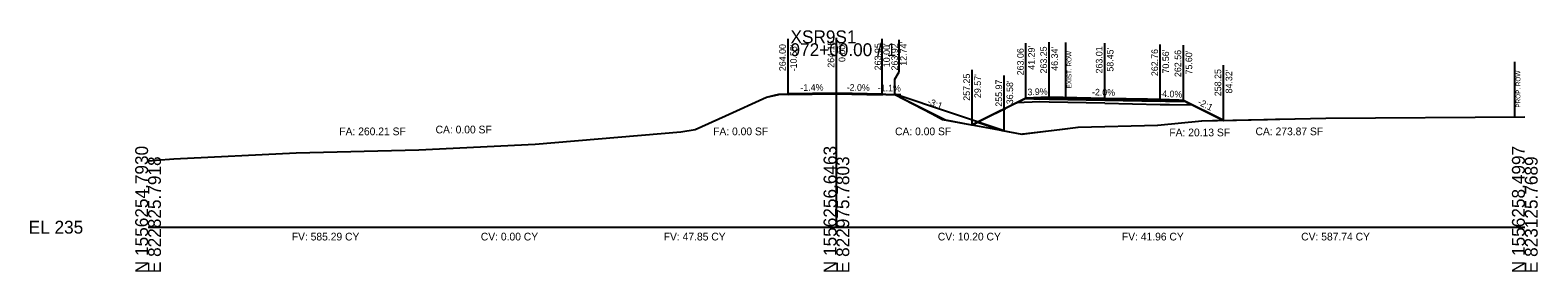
# Model space of a CAD drawing. Extents: x -26 to 823017, y -16 to 1558356.
# Drawn here: x 1974.3 to 2302.8, y 2990.3 to 3042.8 of the extents above; entities that cross this region are included whole.
import ezdxf

# ---------------------------------------------------------------- set-up
doc = ezdxf.new("R2010")
doc.units = 0
for name, color, linetype in [('ASPHALT_19MM1', 7, 'Continuous'), ('CONST_DCH', 7, 'Continuous'), ('CONST_LV3', 7, 'Continuous'), ('Draft_XS_Grid', 7, 'Continuous'), ('DTM_CORRIDOR', 7, 'Continuous'), ('DTM_P_FINISHED_GRADE2', 7, 'Continuous'), ('DTM_X_GROUND', 7, 'Continuous'), ('SLOPE_STAKES_FILL', 7, 'Continuous'), ('X_PROFILES_1', 7, 'Continuous'), ('X_TRANS_EOP', 7, 'Continuous'), ('XS_CELL', 7, 'Continuous'), ('XS_P_ASPHALT', 7, 'Continuous'), ('XS_P_DR_GRAVEL', 7, 'Continuous'), ('XS_P_GROUND', 7, 'Continuous'), ('XS_P_NULL_POINT', 7, 'Continuous'), ('XS_P_ROW', 7, 'Continuous'), ('XS_P_SHOULDER', 7, 'Continuous'), ('XS_P_SUBGRADE_GRANULAR', 7, 'Continuous'), ('XS_P_SUBGRADE_LEVELING', 7, 'Continuous'), ('XS_P_SUBGRADE_MILLING', 7, 'Continuous'), ('XS_P_SUBGRADE_UNDERCUT', 7, 'Continuous'), ('XS_P_TX_CLEARZONE', 7, 'Continuous'), ('XS_P_TX_FS_BS', 7, 'Continuous'), ('XS_SHEET_EW_TX_AREA', 7, 'Continuous'), ('XS_SHEET_EW_TX_VOLUME', 7, 'Continuous'), ('XS_X_ROW', 7, 'Continuous')]:
    doc.layers.add(name, color=color, linetype=linetype)

msp = doc.modelspace()

# ---------------------------------------------------------------- linework, layer by layer
at = {"layer": 'ASPHALT_19MM1'}
msp.add_lwpolyline([(2196.34, 3027.88), (2208.45, 3027.63), (2220.56, 3027.39), (2220.56, 3027.6), (2208.45, 3027.84), (2196.34, 3028.09), (2196.34, 3027.88)], dxfattribs=at)
at = {"layer": 'CONST_LV3'}
for points in [[(2150, 3029.15), (2164, 3028.87)], [(2000, 3014.41), (2001.8, 3014.55), (2005.65, 3014.87), (2032.3, 3016.21), (2058.98, 3016.83), (2084.32, 3018.03), (2116.06, 3020.73), (2119.18, 3021.23), (2125.84, 3024.24), (2134.73, 3028.25), (2136.51, 3028.72), (2137.45, 3028.96), (2137.45, 3028.96), (2137.45, 3028.96), (2137.45, 3028.96)], [(2162.74, 3028.92), (2162.74, 3028.92), (2164, 3028.87)], [(2173.76, 3023.34), (2173.76, 3023.34), (2173.78, 3023.34), (2179.44, 3022.28), (2179.47, 3022.27), (2179.57, 3022.25), (2179.79, 3022.36), (2183.24, 3024.07), (2185.93, 3025.4), (2186.82, 3025.84), (2186.86, 3025.86), (2191.29, 3028.06), (2194.56, 3028.18), (2196.34, 3028.25), (2204.83, 3028.08), (2208.45, 3028.01), (2211.6, 3027.85), (2220.56, 3027.39), (2224.62, 3027.53), (2225.6, 3027.56), (2226.86, 3026.94), (2227.01, 3026.86), (2228.29, 3026.23), (2229.88, 3025.44), (2234.35, 3023.23), (2236.77, 3023.3), (2237.15, 3023.31), (2243.57, 3023.44), (2243.9, 3023.44), (2245.64, 3023.48), (2245.87, 3023.48), (2246.39, 3023.49), (2246.54, 3023.5), (2246.59, 3023.5), (2256.64, 3023.7), (2300, 3024.02)], [(2179.57, 3022.25), (2186.86, 3025.86), (2191.29, 3028.06), (2194.56, 3028.18), (2196.34, 3028.25)], [(2225.63, 3027.56), (2234.32, 3023.25)]]:
    msp.add_lwpolyline(points, dxfattribs=at)
at = {"layer": 'DTM_P_FINISHED_GRADE2'}
msp.add_lwpolyline([(2137.45, 3028.85), (2137.45, 3028.85), (2137.45, 3028.85), (2139.45, 3028.94), (2139.45, 3028.93), (2150, 3029.15), (2150, 3029.15), (2160, 3028.95), (2160, 3028.95), (2160, 3028.95), (2160.74, 3028.93), (2162.74, 3028.85), (2162.74, 3028.85), (2162.74, 3028.85), (2173.76, 3023.34)], dxfattribs=at)
at = {"layer": 'DTM_X_GROUND'}
for points in [[(2000, 3014.41), (2001.8, 3014.55), (2005.65, 3014.87), (2032.3, 3016.21), (2058.98, 3016.83), (2084.32, 3018.03), (2116.06, 3020.73), (2119.18, 3021.23), (2125.84, 3024.24), (2134.73, 3028.25), (2136.51, 3028.72), (2137.47, 3028.97), (2147.38, 3029.11), (2150.14, 3029.15), (2160.79, 3028.89), (2162.73, 3028.85), (2170.86, 3024.63), (2173.1, 3023.46), (2184.29, 3021.39), (2190.38, 3020.26), (2190.65, 3020.3), (2198.7, 3021.27), (2202.66, 3021.75), (2220.06, 3022.22), (2229.64, 3023.16), (2246.54, 3023.5), (2256.64, 3023.7), (2300, 3024.02)], [(2000, 3014.41), (2001.8, 3014.55), (2005.65, 3014.87), (2032.3, 3016.21), (2058.98, 3016.83), (2084.32, 3018.03), (2116.06, 3020.73), (2119.18, 3021.23), (2125.84, 3024.24), (2134.73, 3028.25), (2136.51, 3028.72), (2137.47, 3028.97), (2147.38, 3029.11), (2150.14, 3029.15), (2160.79, 3028.89), (2162.73, 3028.85), (2170.86, 3024.63), (2173.1, 3023.46), (2179.44, 3022.28), (2179.57, 3022.25), (2179.79, 3022.36), (2183.24, 3024.07), (2185.93, 3025.4), (2186.82, 3025.84), (2186.86, 3025.86), (2191.29, 3028.06), (2194.56, 3028.18), (2196.34, 3028.25), (2204.83, 3028.08), (2208.45, 3028.01), (2211.6, 3027.85), (2220.56, 3027.39), (2224.62, 3027.53), (2225.6, 3027.56), (2226.86, 3026.94), (2227.01, 3026.86), (2228.29, 3026.23), (2229.88, 3025.44), (2234.35, 3023.23), (2236.77, 3023.3), (2237.15, 3023.31), (2243.57, 3023.44), (2243.9, 3023.44), (2245.64, 3023.48), (2245.87, 3023.48), (2246.39, 3023.49), (2246.54, 3023.5), (2246.59, 3023.5), (2256.64, 3023.7), (2300, 3024.02)], [(2000, 3014.41), (2001.8, 3014.55), (2005.65, 3014.87), (2032.3, 3016.21), (2058.98, 3016.83), (2084.32, 3018.03), (2116.06, 3020.73), (2119.18, 3021.23), (2125.84, 3024.24), (2134.73, 3028.25), (2136.51, 3028.65), (2137.45, 3028.85), (2137.45, 3028.85), (2137.45, 3028.85), (2137.45, 3028.85), (2137.45, 3028.85), (2137.45, 3028.85), (2139.45, 3028.94), (2139.45, 3028.93), (2150, 3029.15), (2150, 3029.15), (2160, 3028.95), (2160, 3028.95), (2160, 3028.95), (2160, 3028.95), (2160, 3028.95), (2160, 3028.95), (2160.74, 3028.93), (2162.74, 3028.85), (2162.74, 3028.85), (2162.74, 3028.85), (2173.76, 3023.34), (2173.76, 3023.34), (2173.76, 3023.34), (2173.78, 3023.34), (2179.44, 3022.28), (2179.47, 3022.27), (2179.57, 3022.25), (2179.79, 3022.36), (2183.24, 3024.07), (2185.93, 3025.4), (2186.82, 3025.84), (2186.86, 3025.86), (2191.29, 3028.06), (2194.56, 3028.18), (2196.34, 3028.25), (2204.83, 3028.08), (2208.45, 3028.01), (2211.6, 3027.85), (2220.56, 3027.39), (2224.62, 3027.53), (2225.6, 3027.56), (2226.86, 3026.94), (2227.01, 3026.86), (2228.29, 3026.23), (2229.88, 3025.44), (2234.35, 3023.23), (2236.77, 3023.3), (2237.15, 3023.31), (2243.57, 3023.44), (2243.9, 3023.44), (2245.64, 3023.48), (2245.87, 3023.48), (2246.39, 3023.49), (2246.54, 3023.5), (2246.59, 3023.5), (2256.64, 3023.7), (2300, 3024.02)]]:
    msp.add_lwpolyline(points, dxfattribs=at)
at = {"layer": 'X_TRANS_EOP'}
msp.add_lwpolyline([(2196.34, 3028.09), (2208.45, 3027.84), (2220.56, 3027.6), (2220.56, 3027.76), (2208.45, 3028.01), (2196.34, 3028.25), (2196.34, 3028.09)], dxfattribs=at)
at = {"layer": 'XS_CELL'}
for p, q in [((2150, 3000), (2150, 3040)), ((2000, 3000), (2150, 3000)), ((2150, 3000), (2300, 3000))]:
    msp.add_line(p, q, dxfattribs=at)
at = {"layer": 'XS_P_ASPHALT'}
msp.add_lwpolyline([(2139.45, 3028.87), (2139.45, 3028.87), (2150, 3029.02), (2150, 3029.02), (2160, 3028.82), (2160, 3028.82), (2160, 3028.82), (2160, 3028.95), (2160, 3028.95), (2150, 3029.15), (2150, 3029.15), (2139.45, 3029), (2139.45, 3028.87)], dxfattribs=at)
at = {"layer": 'XS_P_DR_GRAVEL'}
for points in [[(2194.56, 3028.18), (2191.29, 3028.06), (2191.24, 3028.03), (2191.15, 3027.98), (2193.01, 3027.95), (2196.34, 3027.88), (2196.34, 3028.13), (2196.34, 3028.25), (2194.56, 3028.18)], [(2221.61, 3027.72), (2225.6, 3027.56), (2225.71, 3027.51), (2226.18, 3027.28), (2221.73, 3027.37), (2220.56, 3027.39), (2220.56, 3027.68), (2220.56, 3027.76), (2221.61, 3027.72)]]:
    msp.add_lwpolyline(points, dxfattribs=at)
at = {"layer": 'XS_P_GROUND'}
for points in [[(2186.58, 3020.97), (2162.74, 3028.92), (2162.74, 3028.92)], [(2191.29, 3028.06), (2179.57, 3022.25)], [(2225.6, 3027.56), (2234.35, 3023.23)], [(2186.58, 3020.97), (2186.58, 3020.97), (2190.38, 3020.26), (2190.65, 3020.3), (2190.65, 3020.3), (2198.7, 3021.27), (2198.7, 3021.27), (2202.66, 3021.75), (2202.66, 3021.75), (2220.06, 3022.22), (2220.06, 3022.22), (2229.64, 3023.16), (2229.64, 3023.16), (2234.32, 3023.25), (2234.32, 3023.25)], [(2186.58, 3020.97), (2186.58, 3020.97), (2190.38, 3020.26), (2190.65, 3020.3), (2190.65, 3020.3), (2198.7, 3021.27), (2198.7, 3021.27), (2202.66, 3021.75), (2202.66, 3021.75), (2220.06, 3022.22), (2220.06, 3022.22), (2229.64, 3023.16), (2229.64, 3023.16), (2234.32, 3023.25), (2234.32, 3023.25)]]:
    msp.add_lwpolyline(points, dxfattribs=at)
at = {"layer": 'XS_P_ROW'}
msp.add_line((2297.83, 3024), (2297.83, 3036), dxfattribs=at)
at = {"layer": 'XS_P_SHOULDER'}
for points in [[(2191.29, 3028.06), (2194.56, 3028.18), (2196.34, 3028.25)], [(2225.6, 3027.56), (2221.61, 3027.72), (2220.56, 3027.76)]]:
    msp.add_lwpolyline(points, dxfattribs=at)
at = {"layer": 'XS_P_SUBGRADE_GRANULAR'}
for points in [[(2196.34, 3027.21), (2194.32, 3027.25), (2189.27, 3027.06)], [(2208.45, 3026.97), (2196.34, 3027.21)], [(2208.45, 3026.97), (2220.56, 3026.72)], [(2220.56, 3026.72), (2222.58, 3026.68), (2227.58, 3026.58)]]:
    msp.add_lwpolyline(points, dxfattribs=at)
at = {"layer": 'XS_P_SUBGRADE_LEVELING'}
msp.add_lwpolyline([(2160, 3028.82), (2160, 3028.82), (2160, 3028.82), (2150.14, 3029.02), (2150.14, 3029.02), (2150, 3029.02), (2147.38, 3028.98), (2147.38, 3028.98), (2139.45, 3028.87), (2139.45, 3028.87)], dxfattribs=at)
msp.add_lwpolyline([(2160, 3028.82), (2160, 3028.82), (2160, 3028.82), (2150.14, 3029.02), (2150.14, 3029.02), (2150, 3029.02), (2147.38, 3028.98), (2147.38, 3028.98), (2139.45, 3028.87), (2139.45, 3028.87)], dxfattribs=at)
at = {"layer": 'XS_P_SUBGRADE_MILLING'}
msp.add_lwpolyline([(2160, 3028.91), (2160, 3028.91), (2150.14, 3029.15), (2150.14, 3029.15), (2150, 3029.15), (2147.38, 3029.11), (2147.38, 3029.11), (2139.45, 3029), (2139.45, 3029), (2139.45, 3028.87), (2139.45, 3028.87), (2139.45, 3028.87), (2147.38, 3028.98), (2147.38, 3028.98), (2150, 3029.02), (2150.14, 3029.02), (2150.14, 3029.02), (2160, 3028.82), (2160, 3028.82), (2160, 3028.82), (2160, 3028.82), (2160, 3028.91), (2160, 3028.91)], dxfattribs=at)
at = {"layer": 'XS_P_SUBGRADE_UNDERCUT'}
msp.add_lwpolyline([(2180.75, 3022.84), (2186.1, 3021.06), (2190.38, 3020.26), (2202.66, 3021.75), (2220.06, 3022.22), (2229.64, 3023.16), (2234.3, 3023.25), (2225.6, 3027.56), (2224.62, 3027.6), (2220.56, 3027.76), (2217.76, 3027.82), (2208.45, 3028.01), (2204.83, 3028.08), (2196.34, 3028.25), (2194.56, 3028.18), (2191.29, 3028.06)], close=True, dxfattribs=at)
at = {"layer": 'XS_P_TX_CLEARZONE'}
for p, q in [((2139.45, 3029), (2139.45, 3041)), ((2150, 3029.15), (2150, 3041.15)), ((2160, 3028.95), (2160, 3040.95)), ((2163.65, 3033.79), (2163.65, 3040.73)), ((2191.29, 3028.06), (2191.29, 3040.06)), ((2196.34, 3028.25), (2196.34, 3040.25)), ((2208.45, 3028.01), (2208.45, 3040.01)), ((2220.56, 3027.76), (2220.56, 3039.76)), ((2225.6, 3027.56), (2225.6, 3039.56)), ((2162.74, 3032.16), (2163.65, 3033.79)), ((2163.65, 3033.79), (2163.65, 3033.79)), ((2179.57, 3022.25), (2179.57, 3034.25)), ((2186.58, 3020.97), (2186.58, 3032.97)), ((2234.32, 3023.25), (2234.32, 3035.25)), ((2162.74, 3028.92), (2162.74, 3032.16))]:
    msp.add_line(p, q, dxfattribs=at)
at = {"layer": 'XS_X_ROW'}
msp.add_line((2200, 3028.18), (2200, 3040.18), dxfattribs=at)

# ---------------------------------------------------------------- texts
at = {"layer": 'CONST_DCH'}
for p in [(2139.37, 3028.88), (2149.92, 3029.03), (2159.92, 3028.83)]:
    msp.add_text('X', height=0.24, dxfattribs=at).set_placement(p)
at = {"layer": 'CONST_LV3'}
for p in [(2162.66, 3028.8), (2234.24, 3023.13), (2186.51, 3020.85)]:
    msp.add_text('X', height=0.24, dxfattribs=at).set_placement(p)
at = {"layer": 'Draft_XS_Grid'}
msp.add_text('-', height=0.0001, dxfattribs=at).set_placement((2000, 3000))
at = {"layer": 'DTM_CORRIDOR'}
for p in [(2196.26, 3028.13), (2208.37, 3027.89), (2220.48, 3027.64)]:
    msp.add_text('X', height=0.24, dxfattribs=at).set_placement(p)
at = {"layer": 'SLOPE_STAKES_FILL'}
for p in [(2234.27, 3023.11), (2179.49, 3022.13)]:
    msp.add_text('X', height=0.24, dxfattribs=at).set_placement(p)
at = {"layer": 'X_PROFILES_1'}
msp.add_text('X', height=0.24, dxfattribs=at).set_placement((2234.24, 3023.13))
at = {"layer": 'XS_CELL'}
for s, p in [('XSR9S1', (2140, 3040)), ('972+00.00 / 1', (2140, 3037.2)), ('EL 235', (1974, 2998.6))]:
    msp.add_text(s, height=2.8, dxfattribs=at).set_placement(p)
for s, p in [('N 1556254.7930', (2000, 2990)), ('N 1556256.6463', (2150, 2990)), ('N 1556258.4997', (2300, 2990)), ('E 822825.7918', (2002.8, 2990)), ('E 822975.7803', (2152.8, 2990)), ('E 823125.7689', (2302.8, 2990))]:
    msp.add_text(s, height=2.8, rotation=90, dxfattribs=at).set_placement(p)
at = {"layer": 'XS_P_NULL_POINT'}
for p in [(2234.27, 3023.11), (2179.49, 3022.13)]:
    msp.add_text('X', height=0.24, dxfattribs=at).set_placement(p)
at = {"layer": 'XS_P_ROW'}
msp.add_text('PROP. ROW', height=1, rotation=90, dxfattribs=at).set_placement((2299.03, 3026))
at = {"layer": 'XS_P_SHOULDER'}
for p in [(2191.21, 3027.94), (2225.52, 3027.44)]:
    msp.add_text('X', height=0.24, dxfattribs=at).set_placement(p)
at = {"layer": 'XS_P_TX_CLEARZONE'}
for s, p in [('264.00', (2138.97, 3033.94)), ("-10.55'", (2141.37, 3033.9)), ('264.15', (2149.52, 3034.69)), ("0.00'", (2151.92, 3035.93)), ('263.95', (2159.75, 3034.12)), ("10.00'", (2161.65, 3034.8)), ('263.92', (2163.41, 3034.09)), ("12.74'", (2165.31, 3035.11)), ("41.29'", (2193.21, 3034.25)), ('263.25', (2195.86, 3033.43)), ("46.34'", (2198.26, 3034.02)), ('263.01', (2207.97, 3033.44)), ("58.45'", (2210.37, 3033.84)), ('263.06', (2190.81, 3033.04)), ('262.76', (2220.08, 3032.86)), ("70.56'", (2222.48, 3033.42)), ('262.56', (2225.12, 3032.66)), ("75.60'", (2227.52, 3033.22)), ('257.25', (2179.09, 3027.5)), ("29.57'", (2181.49, 3028.09)), ('258.25', (2233.84, 3028.5)), ("84.32'", (2236.24, 3029.09)), ('255.97', (2186.1, 3026.21)), ("36.58'", (2188.5, 3026.74))]:
    msp.add_text(s, height=1.44, rotation=90, dxfattribs=at).set_placement(p)
at = {"layer": 'XS_P_TX_FS_BS'}
for s, rotation, p in [('-1.4%', 0.8071, (2142.16, 3029.64)), ('-2.0%', 358.8542, (2152.22, 3029.7)), ('-1.1%', 359.3812, (2159, 3029.56)), ('3.9%', 2.246, (2191.65, 3028.67)), ('-2.0%', 358.841, (2205.67, 3028.67)), ('-4.0%', 357.7069, (2220.31, 3028.37)), ('-3:1', 338.4036, (2169.69, 3026.81)), ('-2:1', 333.6752, (2228.6, 3026.75))]:
    msp.add_text(s, height=1.44, rotation=rotation, dxfattribs=at).set_placement(p)
at = {"layer": 'XS_SHEET_EW_TX_AREA'}
for s, p in [('FA: 260.21 SF', (2041.67, 3020)), ('CA: 0.00 SF', (2062.65, 3020.4)), ('FA: 0.00 SF', (2123.13, 3020)), ('CA: 0.00 SF', (2162.77, 3020)), ('FA: 20.13 SF', (2222.54, 3019.77)), ('CA: 273.87 SF', (2241.32, 3020))]:
    msp.add_text(s, height=1.68, dxfattribs=at).set_placement(p)
at = {"layer": 'XS_SHEET_EW_TX_VOLUME'}
for s, p in [('FV: 585.29 CY', (2031.31, 2997.12)), ('CV: 0.00 CY', (2072.51, 2997.12)), ('FV: 47.85 CY', (2112.36, 2997.12)), ('CV: 10.20 CY', (2172.09, 2997.12)), ('FV: 41.96 CY', (2212.2, 2997.12)), ('CV: 587.74 CY', (2251.27, 2997.12))]:
    msp.add_text(s, height=1.68, dxfattribs=at).set_placement(p)
at = {"layer": 'XS_X_ROW'}
msp.add_text('EXIST. ROW', height=1, rotation=90, dxfattribs=at).set_placement((2201.2, 3030.18))

doc.saveas('drawing.dxf')
